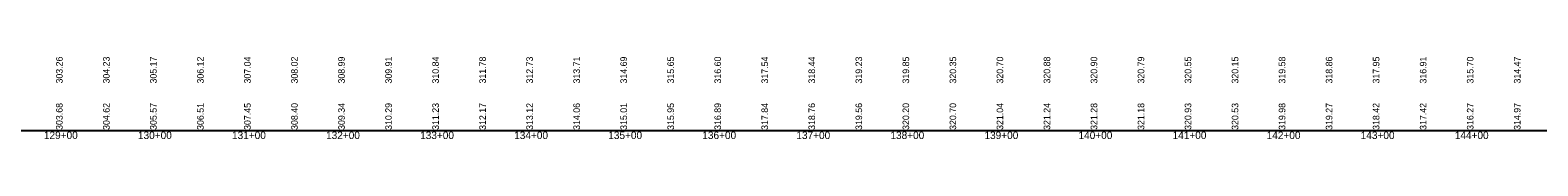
# Model space of a CAD drawing. Extents: x 1876258 to 1932803, y 754739 to 837911.
# Drawn here: x 1891228 to 1892831, y 830495 to 830583 of the extents above; entities that cross this region are included whole.
import ezdxf

# ---------------------------------------------------------------- set-up
doc = ezdxf.new("R2010")
doc.units = 0
for name, color, linetype in [('RD_DDB_StaTX', 7, 'Continuous'), ('RD_DDB_StripGrade', 7, 'Continuous'), ('RD_GPK_Profile_Cell', 7, 'Continuous')]:
    doc.layers.add(name, color=color, linetype=linetype)

msp = doc.modelspace()

# ---------------------------------------------------------------- linework, layer by layer
at = {"layer": 'RD_GPK_Profile_Cell'}
msp.add_line((1878363.1, 830504.3), (1926563.1, 830504.3), dxfattribs=at)

# ---------------------------------------------------------------- texts
at = {"layer": 'RD_DDB_StaTX'}
for s, p in [('129+00', (1891242.2, 830495.3)), ('129+00', (1891242.2, 830495.3)), ('130+00', (1891342.2, 830495.3)), ('130+00', (1891342.2, 830495.3)), ('131+00', (1891442.2, 830495.3)), ('131+00', (1891442.2, 830495.3)), ('132+00', (1891542.2, 830495.3)), ('132+00', (1891542.2, 830495.3)), ('133+00', (1891642.2, 830495.3)), ('133+00', (1891642.2, 830495.3)), ('134+00', (1891742.2, 830495.3)), ('134+00', (1891742.2, 830495.3)), ('135+00', (1891842.2, 830495.3)), ('135+00', (1891842.2, 830495.3)), ('136+00', (1891942.2, 830495.3)), ('136+00', (1891942.2, 830495.3)), ('137+00', (1892042.2, 830495.3)), ('137+00', (1892042.2, 830495.3)), ('138+00', (1892142.2, 830495.3)), ('138+00', (1892142.2, 830495.3)), ('139+00', (1892242.2, 830495.3)), ('139+00', (1892242.2, 830495.3)), ('140+00', (1892342.2, 830495.3)), ('140+00', (1892342.2, 830495.3)), ('141+00', (1892442.2, 830495.3)), ('141+00', (1892442.2, 830495.3)), ('142+00', (1892542.2, 830495.3)), ('142+00', (1892542.2, 830495.3)), ('143+00', (1892642.2, 830495.3)), ('143+00', (1892642.2, 830495.3)), ('144+00', (1892742.2, 830495.3)), ('144+00', (1892742.2, 830495.3))]:
    msp.add_text(s, height=8, dxfattribs=at).set_placement(p)
at = {"layer": 'RD_DDB_StripGrade'}
for s, p in [('303.26', (1891262.1, 830554.3)), ('304.23', (1891312.1, 830554.3)), ('305.17', (1891362.1, 830554.3)), ('306.12', (1891412.1, 830554.3)), ('307.04', (1891462.1, 830554.3)), ('308.02', (1891512.1, 830554.3)), ('308.99', (1891562.1, 830554.3)), ('309.91', (1891612.1, 830554.3)), ('310.84', (1891662.1, 830554.3)), ('311.78', (1891712.1, 830554.3)), ('312.73', (1891762.1, 830554.3)), ('313.71', (1891812.1, 830554.3)), ('314.69', (1891862.1, 830554.3)), ('315.65', (1891912.1, 830554.3)), ('316.60', (1891962.1, 830554.3)), ('317.54', (1892012.1, 830554.3)), ('318.44', (1892062.1, 830554.3)), ('319.23', (1892112.1, 830554.3)), ('319.85', (1892162.1, 830554.3)), ('320.35', (1892212.1, 830554.3)), ('320.70', (1892262.1, 830554.3)), ('320.88', (1892312.1, 830554.3)), ('320.90', (1892362.1, 830554.3)), ('320.79', (1892412.1, 830554.3)), ('320.55', (1892462.1, 830554.3)), ('320.15', (1892512.1, 830554.3)), ('319.58', (1892562.1, 830554.3)), ('318.86', (1892612.1, 830554.3)), ('317.95', (1892662.1, 830554.3)), ('316.91', (1892712.1, 830554.3)), ('315.70', (1892762.1, 830554.3)), ('314.47', (1892812.1, 830554.3)), ('303.68', (1891262.1, 830505)), ('304.62', (1891312.1, 830505)), ('305.57', (1891362.1, 830505)), ('306.51', (1891412.1, 830505)), ('307.45', (1891462.1, 830505)), ('308.40', (1891512.1, 830505)), ('309.34', (1891562.1, 830505)), ('310.29', (1891612.1, 830505)), ('311.23', (1891662.1, 830505)), ('312.17', (1891712.1, 830505)), ('313.12', (1891762.1, 830505)), ('314.06', (1891812.1, 830505)), ('315.01', (1891862.1, 830505)), ('315.95', (1891912.1, 830505)), ('316.89', (1891962.1, 830505)), ('317.84', (1892012.1, 830505)), ('318.76', (1892062.1, 830505)), ('319.56', (1892112.1, 830505)), ('320.20', (1892162.1, 830505)), ('320.70', (1892212.1, 830505)), ('321.04', (1892262.1, 830505)), ('321.24', (1892312.1, 830505)), ('321.28', (1892362.1, 830505)), ('321.18', (1892412.1, 830505)), ('320.93', (1892462.1, 830505)), ('320.53', (1892512.1, 830505)), ('319.98', (1892562.1, 830505)), ('319.27', (1892612.1, 830505)), ('318.42', (1892662.1, 830505)), ('317.42', (1892712.1, 830505)), ('316.27', (1892762.1, 830505)), ('314.97', (1892812.1, 830505))]:
    msp.add_text(s, height=7, rotation=90, dxfattribs=at).set_placement(p)

doc.saveas('drawing.dxf')
